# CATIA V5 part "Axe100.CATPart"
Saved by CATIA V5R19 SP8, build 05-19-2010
Part number: Axe100
Bounding box of the stored display mesh (mm): x 0 to 100, y -15 to 15, z -15 to 15
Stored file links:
  J:\Travail\2e année\IAO\Projet\Axe100.CATPart
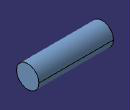
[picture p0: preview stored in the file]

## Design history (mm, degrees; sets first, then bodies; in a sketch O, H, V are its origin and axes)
Body1 (main body)
  Sketch1 on yz-plane, origin (0, 0, 0), H (0, 1, 0), V (0, 0, 1)
    circle A1 centre (0, 0) radius 15
    radius A1 = 15
  Pad1: profile Sketch1, direction (1, 0, 0), length 100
